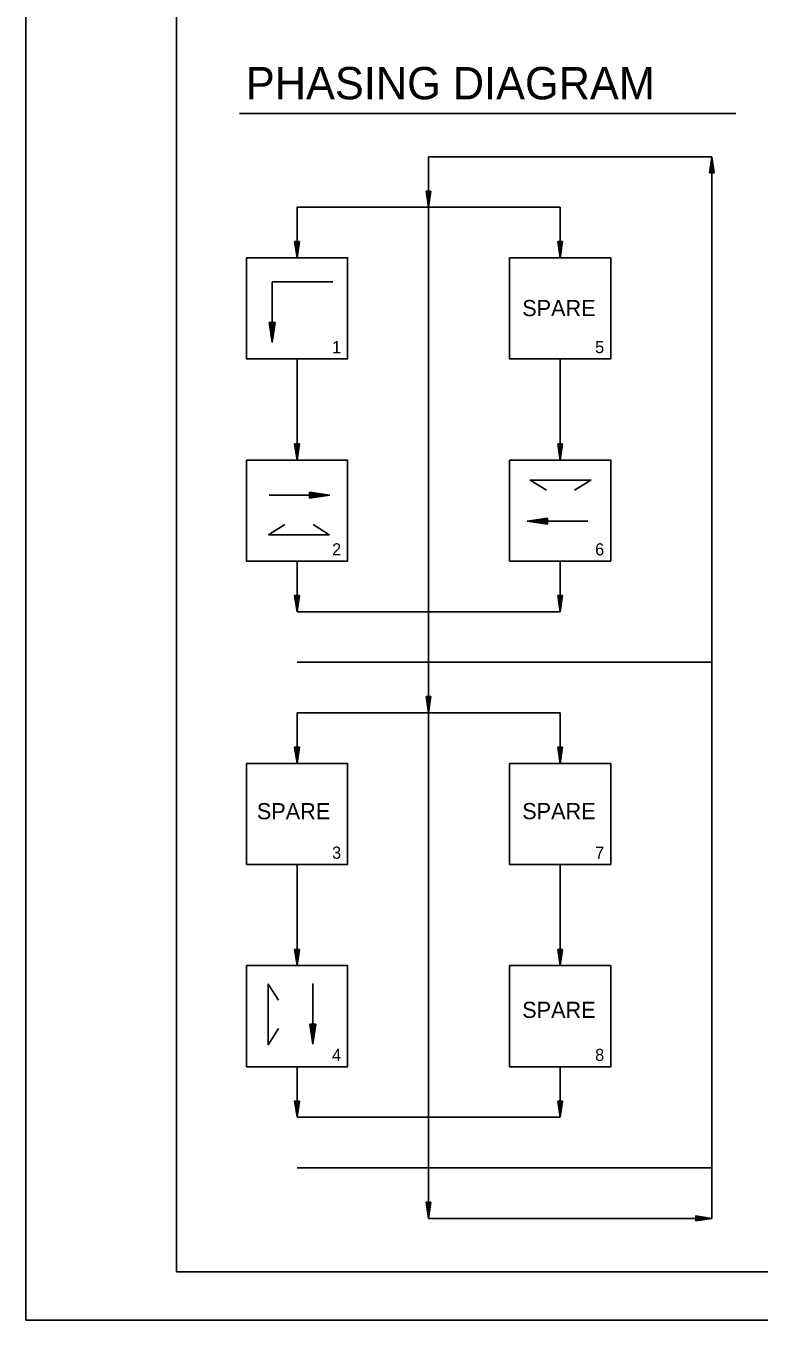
# Model space of a CAD drawing. Extents: x 1280123 to 1281123, y 1892664 to 1893304.
# Drawn here: x 1280122.7 to 1280303.9, y 1892664 to 1892984 of the extents above; entities that cross this region are included whole.
import ezdxf

# ---------------------------------------------------------------- set-up
doc = ezdxf.new("R2010")
doc.units = 0
for name, color, linetype in [('R_Border', 7, 'Continuous'), ('R_Draft', 7, 'Continuous'), ('R_No Plot', 7, 'Continuous'), ('T_Drafting', 7, 'Continuous'), ('T_Notes', 7, 'Continuous')]:
    doc.layers.add(name, color=color, linetype=linetype)

msp = doc.modelspace()

# ---------------------------------------------------------------- linework, layer by layer
at = {"layer": 'R_Border'}
for p, q in [((1280159.93, 1892675.97), (1280159.93, 1893292.35)), ((1280159.93, 1892675.97), (1280159.93, 1892675.97)), ((1281108.47, 1892675.97), (1280159.93, 1892675.97))]:
    msp.add_line(p, q, dxfattribs=at)
at = {"layer": 'R_Draft'}
for p, q in [((1280291.59, 1892947.68), (1280292.19, 1892951.68)), ((1280291.69, 1892947.68), (1280292.19, 1892951.01)), ((1280291.79, 1892947.68), (1280292.19, 1892950.32)), ((1280292.79, 1892947.68), (1280292.19, 1892951.68)), ((1280292.69, 1892947.68), (1280292.19, 1892951.01)), ((1280292.59, 1892947.68), (1280292.19, 1892950.32)), ((1280291.59, 1892947.68), (1280292.79, 1892947.68)), ((1280291.89, 1892947.68), (1280292.19, 1892949.66)), ((1280292, 1892947.68), (1280292.19, 1892948.98)), ((1280292.1, 1892947.68), (1280292.19, 1892948.31)), ((1280292.49, 1892947.68), (1280292.19, 1892949.66)), ((1280292.39, 1892947.68), (1280292.19, 1892948.98)), ((1280292.29, 1892947.68), (1280292.19, 1892948.31)), ((1280221.59, 1892943.18), (1280222.19, 1892939.18)), ((1280222.79, 1892943.18), (1280221.59, 1892943.18)), ((1280221.69, 1892943.18), (1280222.19, 1892939.85)), ((1280221.79, 1892943.18), (1280222.19, 1892940.53)), ((1280221.89, 1892943.18), (1280222.19, 1892941.2)), ((1280222, 1892943.18), (1280222.19, 1892941.88)), ((1280222.1, 1892943.18), (1280222.19, 1892942.55)), ((1280222.79, 1892943.18), (1280222.19, 1892939.18)), ((1280222.39, 1892943.18), (1280222.19, 1892941.88)), ((1280222.59, 1892943.18), (1280222.19, 1892940.53)), ((1280222.69, 1892943.18), (1280222.19, 1892939.85)), ((1280222.49, 1892943.18), (1280222.19, 1892941.2)), ((1280222.29, 1892943.18), (1280222.19, 1892942.55)), ((1280189.09, 1892930.68), (1280189.69, 1892926.68)), ((1280190.29, 1892930.68), (1280189.09, 1892930.68)), ((1280189.19, 1892930.68), (1280189.69, 1892927.35)), ((1280189.29, 1892930.68), (1280189.69, 1892928.03)), ((1280189.39, 1892930.68), (1280189.69, 1892928.7)), ((1280189.5, 1892930.68), (1280189.69, 1892929.38)), ((1280189.6, 1892930.68), (1280189.69, 1892930.05)), ((1280190.29, 1892930.68), (1280189.69, 1892926.68)), ((1280189.89, 1892930.68), (1280189.69, 1892929.38)), ((1280190.09, 1892930.68), (1280189.69, 1892928.03)), ((1280190.19, 1892930.68), (1280189.69, 1892927.35)), ((1280189.99, 1892930.68), (1280189.69, 1892928.7)), ((1280189.79, 1892930.68), (1280189.69, 1892930.05)), ((1280254.09, 1892930.68), (1280254.69, 1892926.68)), ((1280255.29, 1892930.68), (1280254.09, 1892930.68)), ((1280254.19, 1892930.68), (1280254.69, 1892927.35)), ((1280254.29, 1892930.68), (1280254.69, 1892928.03)), ((1280254.39, 1892930.68), (1280254.69, 1892928.7)), ((1280254.5, 1892930.68), (1280254.69, 1892929.38)), ((1280254.6, 1892930.68), (1280254.69, 1892930.05)), ((1280255.29, 1892930.68), (1280254.69, 1892926.68)), ((1280254.89, 1892930.68), (1280254.69, 1892929.38)), ((1280255.09, 1892930.68), (1280254.69, 1892928.03)), ((1280255.19, 1892930.68), (1280254.69, 1892927.35)), ((1280254.99, 1892930.68), (1280254.69, 1892928.7)), ((1280254.79, 1892930.68), (1280254.69, 1892930.05)), ((1280189.09, 1892880.68), (1280189.69, 1892876.68)), ((1280190.29, 1892880.68), (1280189.09, 1892880.68)), ((1280189.19, 1892880.68), (1280189.69, 1892877.35)), ((1280189.29, 1892880.68), (1280189.69, 1892878.03)), ((1280189.39, 1892880.68), (1280189.69, 1892878.7)), ((1280189.5, 1892880.68), (1280189.69, 1892879.38)), ((1280189.6, 1892880.68), (1280189.69, 1892880.05)), ((1280190.29, 1892880.68), (1280189.69, 1892876.68)), ((1280189.89, 1892880.68), (1280189.69, 1892879.38)), ((1280190.09, 1892880.68), (1280189.69, 1892878.03)), ((1280190.19, 1892880.68), (1280189.69, 1892877.35)), ((1280189.99, 1892880.68), (1280189.69, 1892878.7)), ((1280189.79, 1892880.68), (1280189.69, 1892880.05)), ((1280254.09, 1892880.68), (1280254.69, 1892876.68)), ((1280255.29, 1892880.68), (1280254.09, 1892880.68)), ((1280254.19, 1892880.68), (1280254.69, 1892877.35)), ((1280254.29, 1892880.68), (1280254.69, 1892878.03)), ((1280254.39, 1892880.68), (1280254.69, 1892878.7)), ((1280254.5, 1892880.68), (1280254.69, 1892879.38)), ((1280254.6, 1892880.68), (1280254.69, 1892880.05)), ((1280255.29, 1892880.68), (1280254.69, 1892876.68)), ((1280254.89, 1892880.68), (1280254.69, 1892879.38)), ((1280255.09, 1892880.68), (1280254.69, 1892878.03)), ((1280255.19, 1892880.68), (1280254.69, 1892877.35)), ((1280254.99, 1892880.68), (1280254.69, 1892878.7)), ((1280254.79, 1892880.68), (1280254.69, 1892880.05)), ((1280189.09, 1892843.18), (1280189.69, 1892839.18)), ((1280190.29, 1892843.18), (1280189.09, 1892843.18)), ((1280189.19, 1892843.18), (1280189.69, 1892839.85)), ((1280189.29, 1892843.18), (1280189.69, 1892840.53)), ((1280189.39, 1892843.18), (1280189.69, 1892841.2)), ((1280189.5, 1892843.18), (1280189.69, 1892841.88)), ((1280189.6, 1892843.18), (1280189.69, 1892842.55)), ((1280190.29, 1892843.18), (1280189.69, 1892839.18)), ((1280189.89, 1892843.18), (1280189.69, 1892841.88)), ((1280190.09, 1892843.18), (1280189.69, 1892840.53)), ((1280190.19, 1892843.18), (1280189.69, 1892839.85)), ((1280189.99, 1892843.18), (1280189.69, 1892841.2)), ((1280189.79, 1892843.18), (1280189.69, 1892842.55)), ((1280254.09, 1892843.18), (1280254.69, 1892839.18)), ((1280255.29, 1892843.18), (1280254.09, 1892843.18)), ((1280254.19, 1892843.18), (1280254.69, 1892839.85)), ((1280254.29, 1892843.18), (1280254.69, 1892840.53)), ((1280254.39, 1892843.18), (1280254.69, 1892841.2)), ((1280254.5, 1892843.18), (1280254.69, 1892841.88)), ((1280254.6, 1892843.18), (1280254.69, 1892842.55)), ((1280255.29, 1892843.18), (1280254.69, 1892839.18)), ((1280254.89, 1892843.18), (1280254.69, 1892841.88)), ((1280255.09, 1892843.18), (1280254.69, 1892840.53)), ((1280255.19, 1892843.18), (1280254.69, 1892839.85)), ((1280254.99, 1892843.18), (1280254.69, 1892841.2)), ((1280254.79, 1892843.18), (1280254.69, 1892842.55)), ((1280221.59, 1892818.18), (1280222.19, 1892814.18)), ((1280222.79, 1892818.18), (1280221.59, 1892818.18)), ((1280221.69, 1892818.18), (1280222.19, 1892814.85)), ((1280221.79, 1892818.18), (1280222.19, 1892815.53)), ((1280221.89, 1892818.18), (1280222.19, 1892816.2)), ((1280222, 1892818.18), (1280222.19, 1892816.88)), ((1280222.1, 1892818.18), (1280222.19, 1892817.55)), ((1280222.79, 1892818.18), (1280222.19, 1892814.18)), ((1280222.39, 1892818.18), (1280222.19, 1892816.88)), ((1280222.59, 1892818.18), (1280222.19, 1892815.53)), ((1280222.69, 1892818.18), (1280222.19, 1892814.85)), ((1280222.49, 1892818.18), (1280222.19, 1892816.2)), ((1280222.29, 1892818.18), (1280222.19, 1892817.55)), ((1280189.09, 1892805.68), (1280189.69, 1892801.68)), ((1280190.29, 1892805.68), (1280189.09, 1892805.68)), ((1280189.19, 1892805.68), (1280189.69, 1892802.35)), ((1280189.29, 1892805.68), (1280189.69, 1892803.03)), ((1280189.39, 1892805.68), (1280189.69, 1892803.7)), ((1280189.5, 1892805.68), (1280189.69, 1892804.38)), ((1280189.6, 1892805.68), (1280189.69, 1892805.05)), ((1280190.29, 1892805.68), (1280189.69, 1892801.68)), ((1280189.89, 1892805.68), (1280189.69, 1892804.38)), ((1280190.09, 1892805.68), (1280189.69, 1892803.03)), ((1280190.19, 1892805.68), (1280189.69, 1892802.35)), ((1280189.99, 1892805.68), (1280189.69, 1892803.7)), ((1280189.79, 1892805.68), (1280189.69, 1892805.05)), ((1280254.09, 1892805.68), (1280254.69, 1892801.68)), ((1280255.29, 1892805.68), (1280254.09, 1892805.68)), ((1280254.19, 1892805.68), (1280254.69, 1892802.35)), ((1280254.29, 1892805.68), (1280254.69, 1892803.03)), ((1280254.39, 1892805.68), (1280254.69, 1892803.7)), ((1280254.5, 1892805.68), (1280254.69, 1892804.38)), ((1280254.6, 1892805.68), (1280254.69, 1892805.05)), ((1280255.29, 1892805.68), (1280254.69, 1892801.68)), ((1280254.89, 1892805.68), (1280254.69, 1892804.38)), ((1280255.09, 1892805.68), (1280254.69, 1892803.03)), ((1280255.19, 1892805.68), (1280254.69, 1892802.35)), ((1280254.99, 1892805.68), (1280254.69, 1892803.7)), ((1280254.79, 1892805.68), (1280254.69, 1892805.05)), ((1280189.09, 1892755.68), (1280189.69, 1892751.68)), ((1280190.29, 1892755.68), (1280189.09, 1892755.68)), ((1280189.19, 1892755.68), (1280189.69, 1892752.35)), ((1280189.29, 1892755.68), (1280189.69, 1892753.03)), ((1280189.39, 1892755.68), (1280189.69, 1892753.7)), ((1280189.5, 1892755.68), (1280189.69, 1892754.38)), ((1280189.6, 1892755.68), (1280189.69, 1892755.05)), ((1280190.29, 1892755.68), (1280189.69, 1892751.68)), ((1280189.89, 1892755.68), (1280189.69, 1892754.38)), ((1280190.09, 1892755.68), (1280189.69, 1892753.03)), ((1280190.19, 1892755.68), (1280189.69, 1892752.35)), ((1280189.99, 1892755.68), (1280189.69, 1892753.7)), ((1280189.79, 1892755.68), (1280189.69, 1892755.05)), ((1280254.09, 1892755.68), (1280254.69, 1892751.68)), ((1280255.29, 1892755.68), (1280254.09, 1892755.68)), ((1280254.19, 1892755.68), (1280254.69, 1892752.35)), ((1280254.29, 1892755.68), (1280254.69, 1892753.03)), ((1280254.39, 1892755.68), (1280254.69, 1892753.7)), ((1280254.5, 1892755.68), (1280254.69, 1892754.38)), ((1280254.6, 1892755.68), (1280254.69, 1892755.05)), ((1280255.29, 1892755.68), (1280254.69, 1892751.68)), ((1280254.89, 1892755.68), (1280254.69, 1892754.38)), ((1280255.09, 1892755.68), (1280254.69, 1892753.03)), ((1280255.19, 1892755.68), (1280254.69, 1892752.35)), ((1280254.99, 1892755.68), (1280254.69, 1892753.7)), ((1280254.79, 1892755.68), (1280254.69, 1892755.05)), ((1280189.09, 1892718.18), (1280189.69, 1892714.18)), ((1280190.29, 1892718.18), (1280189.09, 1892718.18)), ((1280189.19, 1892718.18), (1280189.69, 1892714.85)), ((1280189.29, 1892718.18), (1280189.69, 1892715.53)), ((1280189.39, 1892718.18), (1280189.69, 1892716.2)), ((1280189.5, 1892718.18), (1280189.69, 1892716.88)), ((1280189.6, 1892718.18), (1280189.69, 1892717.55)), ((1280190.29, 1892718.18), (1280189.69, 1892714.18)), ((1280189.89, 1892718.18), (1280189.69, 1892716.88)), ((1280190.09, 1892718.18), (1280189.69, 1892715.53)), ((1280190.19, 1892718.18), (1280189.69, 1892714.85)), ((1280189.99, 1892718.18), (1280189.69, 1892716.2)), ((1280189.79, 1892718.18), (1280189.69, 1892717.55)), ((1280254.09, 1892718.18), (1280254.69, 1892714.18)), ((1280255.29, 1892718.18), (1280254.09, 1892718.18)), ((1280254.19, 1892718.18), (1280254.69, 1892714.85)), ((1280254.29, 1892718.18), (1280254.69, 1892715.53)), ((1280254.39, 1892718.18), (1280254.69, 1892716.2)), ((1280254.5, 1892718.18), (1280254.69, 1892716.88)), ((1280254.6, 1892718.18), (1280254.69, 1892717.55)), ((1280255.29, 1892718.18), (1280254.69, 1892714.18)), ((1280254.89, 1892718.18), (1280254.69, 1892716.88)), ((1280255.09, 1892718.18), (1280254.69, 1892715.53)), ((1280255.19, 1892718.18), (1280254.69, 1892714.85)), ((1280254.99, 1892718.18), (1280254.69, 1892716.2)), ((1280254.79, 1892718.18), (1280254.69, 1892717.55)), ((1280221.59, 1892693.18), (1280222.19, 1892689.18)), ((1280222.79, 1892693.18), (1280221.59, 1892693.18)), ((1280221.69, 1892693.18), (1280222.19, 1892689.85)), ((1280221.79, 1892693.18), (1280222.19, 1892690.53)), ((1280221.89, 1892693.18), (1280222.19, 1892691.2)), ((1280222, 1892693.18), (1280222.19, 1892691.88)), ((1280222.1, 1892693.18), (1280222.19, 1892692.55)), ((1280222.79, 1892693.18), (1280222.19, 1892689.18)), ((1280222.39, 1892693.18), (1280222.19, 1892691.88)), ((1280222.59, 1892693.18), (1280222.19, 1892690.53)), ((1280222.69, 1892693.18), (1280222.19, 1892689.85)), ((1280222.49, 1892693.18), (1280222.19, 1892691.2)), ((1280222.29, 1892693.18), (1280222.19, 1892692.55)), ((1280288.19, 1892689.78), (1280292.19, 1892689.18)), ((1280288.19, 1892689.78), (1280288.19, 1892688.58)), ((1280288.19, 1892689.68), (1280291.52, 1892689.18)), ((1280288.19, 1892689.58), (1280290.84, 1892689.18)), ((1280288.19, 1892689.48), (1280290.17, 1892689.18)), ((1280288.19, 1892689.37), (1280289.49, 1892689.18)), ((1280288.19, 1892689.27), (1280288.82, 1892689.18)), ((1280288.19, 1892688.58), (1280292.19, 1892689.18)), ((1280288.19, 1892688.98), (1280289.49, 1892689.18)), ((1280288.19, 1892688.78), (1280290.84, 1892689.18)), ((1280288.19, 1892688.68), (1280291.52, 1892689.18)), ((1280288.19, 1892688.88), (1280290.17, 1892689.18)), ((1280288.19, 1892689.08), (1280288.82, 1892689.18))]:
    msp.add_line(p, q, dxfattribs=at)
at = {"layer": 'R_No Plot'}
msp.add_line((1280122.72, 1892664.03), (1281122.72, 1892664.03), dxfattribs=at)
msp.add_lwpolyline([(1280122.7, 1893304.03), (1281122.72, 1893304.03), (1281122.72, 1892664.02), (1280122.7, 1892664.02)], close=True, dxfattribs=at)
at = {"layer": 'T_Drafting'}
for p, q in [((1280222.19, 1892689.18), (1280222.19, 1892951.68)), ((1280222.19, 1892951.68), (1280292.19, 1892951.68)), ((1280292.19, 1892951.68), (1280292.19, 1892689.18)), ((1280189.69, 1892926.68), (1280189.69, 1892939.18)), ((1280189.69, 1892939.18), (1280254.69, 1892939.18)), ((1280254.69, 1892926.68), (1280254.69, 1892939.18)), ((1280198.58, 1892920.7), (1280183.58, 1892920.7)), ((1280183.58, 1892920.7), (1280183.58, 1892905.7)), ((1280183.58, 1892905.7), (1280182.83, 1892910.7)), ((1280184.33, 1892910.7), (1280182.83, 1892910.7)), ((1280182.96, 1892910.7), (1280183.58, 1892906.54)), ((1280183.58, 1892907.4), (1280183.08, 1892910.7)), ((1280183.21, 1892910.7), (1280183.58, 1892908.23)), ((1280183.58, 1892909.08), (1280183.34, 1892910.7)), ((1280183.46, 1892910.7), (1280183.58, 1892909.91)), ((1280183.58, 1892909.91), (1280183.7, 1892910.7)), ((1280183.82, 1892910.7), (1280183.58, 1892909.08)), ((1280183.58, 1892908.23), (1280183.95, 1892910.7)), ((1280184.08, 1892910.7), (1280183.58, 1892907.4)), ((1280183.58, 1892906.54), (1280184.21, 1892910.7)), ((1280184.33, 1892910.7), (1280183.58, 1892905.7)), ((1280189.69, 1892876.68), (1280189.69, 1892901.68)), ((1280254.69, 1892876.68), (1280254.69, 1892901.68)), ((1280182.78, 1892868), (1280197.78, 1892868)), ((1280192.78, 1892868.75), (1280197.78, 1892868)), ((1280192.78, 1892868.75), (1280192.78, 1892867.25)), ((1280196.95, 1892868), (1280192.78, 1892868.63)), ((1280192.78, 1892868.5), (1280196.09, 1892868)), ((1280195.25, 1892868), (1280192.78, 1892868.38)), ((1280192.78, 1892868.25), (1280194.41, 1892868)), ((1280193.57, 1892868), (1280192.78, 1892868.12)), ((1280197.78, 1892868), (1280192.78, 1892867.25)), ((1280192.78, 1892867.38), (1280196.95, 1892868)), ((1280196.09, 1892868), (1280192.78, 1892867.51)), ((1280192.78, 1892867.63), (1280195.25, 1892868)), ((1280194.41, 1892868), (1280192.78, 1892867.76)), ((1280192.78, 1892867.89), (1280193.57, 1892868)), ((1280246.55, 1892861.54), (1280251.55, 1892862.29)), ((1280261.55, 1892861.54), (1280246.55, 1892861.54)), ((1280251.55, 1892860.79), (1280246.55, 1892861.54)), ((1280251.55, 1892862.17), (1280247.39, 1892861.54)), ((1280247.39, 1892861.54), (1280251.55, 1892860.92)), ((1280248.25, 1892861.54), (1280251.55, 1892862.04)), ((1280251.55, 1892861.04), (1280248.25, 1892861.54)), ((1280251.55, 1892861.91), (1280249.08, 1892861.54)), ((1280249.08, 1892861.54), (1280251.55, 1892861.17)), ((1280249.93, 1892861.54), (1280251.55, 1892861.79)), ((1280251.55, 1892861.3), (1280249.93, 1892861.54)), ((1280251.55, 1892861.66), (1280250.76, 1892861.54)), ((1280250.76, 1892861.54), (1280251.55, 1892861.42)), ((1280251.55, 1892860.79), (1280251.55, 1892862.29)), ((1280189.69, 1892839.18), (1280189.69, 1892851.68)), ((1280254.69, 1892839.18), (1280254.69, 1892851.68)), ((1280189.69, 1892839.18), (1280254.69, 1892839.18)), ((1280189.69, 1892826.68), (1280292.19, 1892826.68)), ((1280189.69, 1892814.18), (1280254.69, 1892814.18)), ((1280189.69, 1892801.68), (1280189.69, 1892814.18)), ((1280254.69, 1892801.68), (1280254.69, 1892814.18)), ((1280189.69, 1892751.68), (1280189.69, 1892776.68)), ((1280254.69, 1892751.68), (1280254.69, 1892776.68)), ((1280193.62, 1892747.21), (1280193.62, 1892732.21)), ((1280193.62, 1892732.21), (1280192.87, 1892737.21)), ((1280194.37, 1892737.21), (1280192.87, 1892737.21)), ((1280193, 1892737.21), (1280193.62, 1892733.04)), ((1280193.62, 1892733.9), (1280193.13, 1892737.21)), ((1280193.25, 1892737.21), (1280193.62, 1892734.73)), ((1280193.62, 1892735.58), (1280193.38, 1892737.21)), ((1280193.51, 1892737.21), (1280193.62, 1892736.42)), ((1280193.62, 1892736.42), (1280193.74, 1892737.21)), ((1280193.87, 1892737.21), (1280193.62, 1892735.58)), ((1280193.62, 1892734.73), (1280194, 1892737.21)), ((1280194.12, 1892737.21), (1280193.62, 1892733.9)), ((1280193.62, 1892733.04), (1280194.25, 1892737.21)), ((1280194.37, 1892737.21), (1280193.62, 1892732.21)), ((1280189.69, 1892714.18), (1280189.69, 1892726.68)), ((1280254.69, 1892714.18), (1280254.69, 1892726.68)), ((1280189.69, 1892714.18), (1280254.69, 1892714.18)), ((1280189.69, 1892701.68), (1280292.19, 1892701.68)), ((1280222.19, 1892689.18), (1280292.19, 1892689.18))]:
    msp.add_line(p, q, dxfattribs=at)
for points in [[(1280177.19, 1892926.68), (1280202.19, 1892926.68), (1280202.19, 1892901.68), (1280177.19, 1892901.68)], [(1280242.19, 1892926.68), (1280267.19, 1892926.68), (1280267.19, 1892901.68), (1280242.19, 1892901.68)], [(1280177.19, 1892876.68), (1280202.19, 1892876.68), (1280202.19, 1892851.68), (1280177.19, 1892851.68)], [(1280242.19, 1892876.68), (1280267.19, 1892876.68), (1280267.19, 1892851.68), (1280242.19, 1892851.68)], [(1280177.19, 1892801.68), (1280202.19, 1892801.68), (1280202.19, 1892776.68), (1280177.19, 1892776.68)], [(1280242.19, 1892801.68), (1280267.19, 1892801.68), (1280267.19, 1892776.68), (1280242.19, 1892776.68)], [(1280177.19, 1892751.68), (1280202.19, 1892751.68), (1280202.19, 1892726.68), (1280177.19, 1892726.68)], [(1280242.19, 1892751.68), (1280267.19, 1892751.68), (1280267.19, 1892726.68), (1280242.19, 1892726.68)]]:
    msp.add_lwpolyline(points, close=True, dxfattribs=at)
for points in [[(1280251.29, 1892869.2), (1280247.29, 1892871.7), (1280262.29, 1892871.7), (1280258.29, 1892869.2)], [(1280186.66, 1892860.72), (1280182.66, 1892858.22), (1280197.66, 1892858.22), (1280193.66, 1892860.72)], [(1280185.1, 1892736.11), (1280182.6, 1892732.11), (1280182.6, 1892747.11), (1280185.1, 1892743.11)]]:
    msp.add_lwpolyline(points, dxfattribs=at)
at = {"layer": 'T_Notes'}
msp.add_line((1280175.46, 1892962.39), (1280298.11, 1892962.39), dxfattribs=at)

# ---------------------------------------------------------------- texts
at = {"layer": 'T_Drafting'}
for p in [(1280245.33, 1892912.25), (1280179.76, 1892787.85), (1280245.33, 1892787.88), (1280245.33, 1892738.73)]:
    msp.add_text('SPARE', height=4, dxfattribs=at).set_placement(p)
at = {"layer": 'T_Notes'}
for s, height, p in [('PHASING DIAGRAM', 8, (1280177.06, 1892965.86)), ('1', 3, (1280198.35, 1892903.1)), ('5', 3, (1280263.35, 1892903.1)), ('2', 3, (1280198.35, 1892853.1)), ('6', 3, (1280263.35, 1892853.1)), ('3', 3, (1280198.35, 1892778.1)), ('7', 3, (1280263.35, 1892778.1)), ('4', 3, (1280198.35, 1892728.1)), ('8', 3, (1280263.35, 1892728.1))]:
    msp.add_text(s, height=height, dxfattribs=at).set_placement(p)

doc.saveas('drawing.dxf')
